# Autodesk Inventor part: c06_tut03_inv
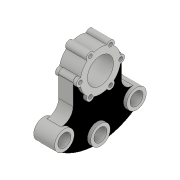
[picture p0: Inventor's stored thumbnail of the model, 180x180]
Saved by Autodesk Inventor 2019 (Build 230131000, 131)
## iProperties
Created: 2015-03
Part Number: c06_tut03_inv
Material: Generic
Document SubType Name: Modeling
Designer: Sandeep
Density: 1 g/cm^3
Appearance: Default
Author: Sandeep
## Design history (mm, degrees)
sketch "Sketch1"
  geometry: L1 (-37, -31.635)-(-37, 0.365); L2 (0, 14.952)-(0, -99.335); L3 (37, 0.365)-(37, -31.635); L4 (-55.203, -64.635)-(-64.945, -76.041); L5 (55.203, -64.635)-(64.945, -76.041); L6 (0, 0)-(41.78, 0); A1 r 31 centre (0, 0) between (30.347, 6.33) and (-30.347, 6.33); A2 r 18 centre (-55, -31.635) between (-55.111, -49.635) and (-37, -31.635); A3 r 15 centre (-55.203, -64.635) between (-55.111, -49.635) and (-64.945, -76.041); A4 r 100 centre (0, 0) between (-64.945, -76.041) and (64.945, -76.041); A5 r 18 centre (55, -31.635) between (37, -31.635) and (55.111, -49.635); A6 r 15 centre (55.203, -64.635) between (64.945, -76.041) and (55.111, -49.635); A7 r 6 centre (-31, 0.365) between (-30.347, 6.33) and (-37, 0.365); A8 r 6 centre (31, 0.365) between (37, 0.365) and (30.347, 6.33); 1 further point
  constraints: 16 point on circle, 12 end point, 8 centre point, 7 tangent, 3 vertical, 2 coincident, 2 symmetric about line, 1 horizontal, 1 parallel, 1 point on line, 3 other
  dimensions: "d0" = 31 radius of A1; "d2" = 18 radius of A5; "d3" = 15 radius of A6; "d4" = 100 radius of A4; "d6" = 81 deg angle of L5 L4; "d7" = 65 vertical distance of L3.start L5.start; "d8" = 6 radius of A7; "d10" = 74 distance between parallel lines of L3 L1
extrude "Extrusion1" new body sketch "Sketch1" stored distance "d11" = 22; taper "d12" = 0 deg
sketch "Sketch5"
  geometry: L1 (0, 48.219)-(0, -124.115); L2 (0, 0)-(43.472, 0); L3 (0, 0)-(17.524, 30.352); A1 r 6 centre (31.011, 0) between (30.42, -5.971) and (30.42, 5.971); A2 r 31 centre (0, 0) between (30.347, 6.33) and (-30.347, 6.33) reference; A3 r 6 centre (15.5, 26.847) between (20.381, 23.358) and (10.038, 29.33); A4 r 31 centre (0, 0) between (30.42, 5.971) and (20.381, 23.358); A5 r 6 centre (-31.011, 0) between (-30.42, 5.971) and (-30.42, -5.971); A6 r 6 centre (-15.5, 26.847) between (-10.038, 29.33) and (-20.381, 23.358); A7 r 6 centre (-15.5, -26.847) between (-20.381, -23.358) and (-10.038, -29.33); A8 r 6 centre (15.5, -26.847) between (10.038, -29.33) and (20.381, -23.358); A9 r 31 centre (0, 0) between (10.038, 29.33) and (-10.038, 29.33); A10 r 31 centre (0, 0) between (-20.381, 23.358) and (-30.42, 5.971); A11 r 31 centre (0, 0) between (-30.42, -5.971) and (-20.381, -23.358); A12 r 31 centre (0, 0) between (-10.038, -29.33) and (10.038, -29.33); A13 r 31 centre (0, 0) between (20.381, -23.358) and (30.42, -5.971); 2 further points
  constraints: 28 point on circle, 12 centre point, 12 symmetric about line, 6 end point, 3 point on line, 1 coincident, 1 horizontal, 1 vertical, 4 other
  dimensions: "d19" = 12 diameter of A1; "d20" = 60 deg angle of L2 L3; "d21" = 12 diameter of A3
extrude "Extrusion2" join sketch "Sketch5" stored distance "d22" = 32; taper "d23" = 0 deg
hole "Hole1" diameter "d26" = 6; stored, may be unused: countersink angle "d30" = 90 deg, drill point angle "d32" = 118 deg; dims "d24" = 10, "d25" = 10, "d27" = 6, "d28" = 4, "d29" = 2, "d31" = 8
pattern_circular "Circular Pattern1" dims angle "d34" = 360 deg
sketch "Sketch6"
  geometry: A1 r 15 centre (-55.203, -64.635) between (-55.111, -49.635) and (-64.945, -76.041) reference; 2 further points
  constraints: 1 coincident, 3 other
extrude "Extrusion3" join sketch "Sketch6" stored distance "d36" = 32; taper "d37" = 0 deg
hole "Hole2" diameter "d40" = 20; stored, may be unused: countersink angle "d44" = 90 deg, drill point angle "d46" = 118 deg; dims "d41" = 6, "d42" = 4, "d43" = 2, "d45" = 8, "d59" = 10, "d60" = 10
pattern_circular "Circular Pattern2" dims angle "d48" = 81 deg
hole "Hole3" diameter "d52" = 40; stored, may be unused: countersink angle "d56" = 90 deg, drill point angle "d58" = 118 deg; dims "d50" = 10, "d51" = 10, "d53" = 6, "d54" = 4, "d55" = 2, "d57" = 8
body "Solid1"
other parameters: "d18" = 62
